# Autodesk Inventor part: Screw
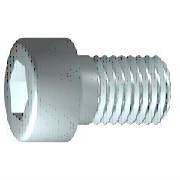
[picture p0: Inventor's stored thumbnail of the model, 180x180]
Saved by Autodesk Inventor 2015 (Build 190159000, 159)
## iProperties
Created: 2005-10
Part Number: Screw
Material: 鋼，軟
Description: 六角承窩頭螺釘
Vendor: Autodesk Inc.
Document SubType Name: Modeling
Standard: ISO 4762
Designer: Power User
Standards Organization: ISO
Language: zh-TW
Size Designation: M10 x 40
Categories: <MemberInstance Version="R10.0.0"><Categories><Category DisplayName="結件" InternalName="e4da775c-781d-43d5-af7c-5136215cf5a6" Mnemonic="FSTN"><Category DisplayNa
Mass: 37.6342 g
Surface Area: 22.7501 cm^2
Volume: 4.79417 cm^3
Density: 7.85 g/cm^3
Appearance: 鋼
Author: Power User
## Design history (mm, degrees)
sketch "草圖1"
  geometry: L1 (-2.333, 0)-(40, 0); L2 (40, 0)-(40, 5); L3 (40, 5)-(3.75, 5); L4 (3.75, 5)-(2.83, 5); L5 (2.83, 5)-(0, 5); L6 (0, 5)-(0, 8); L7 (0, 8)-(-10, 8); L8 (-10, 8)-(-10, 4.619); L9 (-10, 4.619)-(-5, 4.619); L10 (-5, 4.619)-(-2.333, 0); L11 (-15, 0)-(55, 0) reference; L12 (0, -0.8)-(0, 10.4) reference; L13 (3.75, 5)-(0, 5)
  constraints: 22 end point, 6 parallel, 2 collinear, 2 perpendicular, 1 horizontal, 1 point on line
  dimensions: "d1" = 36.25 distance from line of L3.end L2 (= GEL); "d2" = 0.92028 distance of L4.end L3.end (computed from GAL); "d3" = 10 distance between parallel lines of L8 L6 (= KOH); "d4" = 5 distance of L8.end L9.end (= INTI); "d5" = 60 deg angle of L10 L1; "d6" = 10 diameter of L3 L1 (= GD); "d7" = 10 diameter of L5 L1 (= BDM); "d8" = 9.2376 diameter of L9 L1 (= 1.1547 x SW); "d9" = 16 diameter of L7 L1 (= KOD); "d26" = 40 distance between parallel lines of L12 L2 (= NLG)
revolve "本體" sketch "草圖1" stored, may be unused: angle "d10" = 90 deg
sketch "草圖2"
  geometry: L1 (0, -9.6)-(0, 12.8) reference; L2 (-9.6, 0)-(12.8, 0) reference; L3 (4.619, 0)-(2.309, -4); L4 (2.309, -4)-(-2.309, -4); L5 (-2.309, -4)-(-4.619, 0); L6 (-4.619, 0)-(-2.309, 4); L7 (-2.309, 4)-(2.309, 4); L8 (2.309, 4)-(4.619, 0); 2 further points
  constraints: 12 end point, 1 coincident, 1 horizontal alignment, 1 point on line, 12 other
extrude "槽" join sketch "草圖2" stored distance "d11" = 10; taper "d12" = 0 deg
chamfer "去角1" distance "d15" = 0.92018 (= -0.5 x SPD + 0.5 x GD); stored, may be unused: second distance "d16" = 0.92018 (= GUL), angle "d27" = 45 deg
node "實體1"
node "實體本體"
node "曲面本體"
fillet "圓角1" dims "d17" = 1 (= RR)
feature "螺紋" dims "d13" = 36.25 (= GEL), "d14" = 0
other parameters: "GD" = 10 [user parameter; used in 2 equation terms], "NLG" = 40 [user parameter; used in 1 equation term], "GEL" = 36.25 [user parameter; used in 2 equation terms], "KOD" = 16 [user parameter; used in 1 equation term], "KOH" = 10 [user parameter; used in 1 equation term], "INTI" = 5 [user parameter; used in 1 equation term], "GAL" = 0.92018 (= 0.61345 x PTC) [user parameter; used in 1 equation term], "GUL" = 0.92018 (= 0.61345 x PTC) [user parameter; used in 1 equation term], "BDM" = 10 (= NND) [user parameter; used in 1 equation term], "SW" = 8 [user parameter; used in 2 equation terms], "RR" = 1 [user parameter; used in 1 equation term], "SPD" = 8.15965 (= NND - 1.2269 x PTC) [user parameter; used in 1 equation term], "E0" = 9.24 (= 1.155 x SW) [user parameter], "FAWI" = 45 deg [user parameter], "TPU" = 6.66667 (computed from PTC) [user parameter], "GD1" = 8.15965 (= THREADDIA - 1.2269 x PTC) [user parameter], "PTC" = 1.5 [user parameter; used in 5 equation terms], "TOA" = 30 deg [user parameter], "d29" = 0
